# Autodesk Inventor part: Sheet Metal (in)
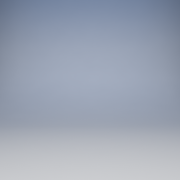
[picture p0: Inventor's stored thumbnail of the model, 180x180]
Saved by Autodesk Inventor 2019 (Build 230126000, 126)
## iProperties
Created: 2018-02
Part Number: Sheet Metal (in)
Material: Všeobecné
Document SubType Name: Plech
Density: 1 g/cm^3
Sheet Metal Rule: Výchozí
Appearance: Výchozí
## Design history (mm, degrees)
other parameters: "Tloušťka" = 3.048 (derived), "KSoučinitel" = 4.4, "PoloměrOhybu" = 3.048 (= Tloušťka), "ŠířkaVýštipu" = 3.048 (= Tloušťka), "HloubkaVýštipu" = 1.524 (= 0.5 x Tloušťka), "VelikostRohovéhoVýštipu" = 12.192 (= 4 x Tloušťka), "MezeraVystřižení" = 0.00508, "MinimálníZbytek" = 6.096 (= 2 x Tloušťka), "PřechodovýPoloměr" = 3.048 (= PoloměrOhybu), "VelikostJacobihoPoloměru" = 3.048 (= PoloměrOhybu), "VelikostMezery" = 3.048 (= Tloušťka)
